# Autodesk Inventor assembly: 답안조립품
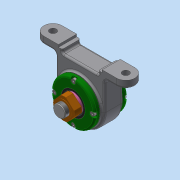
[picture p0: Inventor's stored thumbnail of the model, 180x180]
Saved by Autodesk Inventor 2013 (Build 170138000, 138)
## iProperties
Created: 2019-05
Part Number: 답안조립품
Document SubType Name: Assembly
Designer: dgall
Author: dgall
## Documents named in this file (13)
- C:\Users\dgall\Desktop\490504V1022 (2)\답안조립품.iam
- C:\Users\dgall\Desktop\490504V1022 (2)\본체.ipt
- C:\Users\dgall\Desktop\490504V1022 (2)\앵귤러 볼 베어링 7205.ipt
- C:\Users\dgall\Desktop\490504V1022 (2)\커버.ipt
- C:\Users\dgall\Desktop\490504V1022 (2)\개스킷.ipt
- C:\Users\dgall\Desktop\490504V1022 (2)\축.ipt
- C:\Users\dgall\Desktop\490504V1022 (2)\칼라.ipt
- C:\Users\dgall\Desktop\490504V1022 (2)\오일 실 28 40 5 B.ipt
- C:\Users\dgall\Desktop\490504V1022 (2)\베어링너트.ipt
- C:\Users\dgall\Desktop\490504V1022 (2)\볼트 M4.ipt
- C:\Users\dgall\Desktop\490504V1022 (2)\그리스니플 M6.ipt
- 그리스니플  M6.ipt
- C:\Users\dgall\Desktop\490504V1022 (2)\그리스니플개스킷.ipt
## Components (4 placed, 3 different names)
1. 개스킷:1
2. 개스킷:2
3. 그리스니플  M6:1
4. 그리스니플개스킷:1
